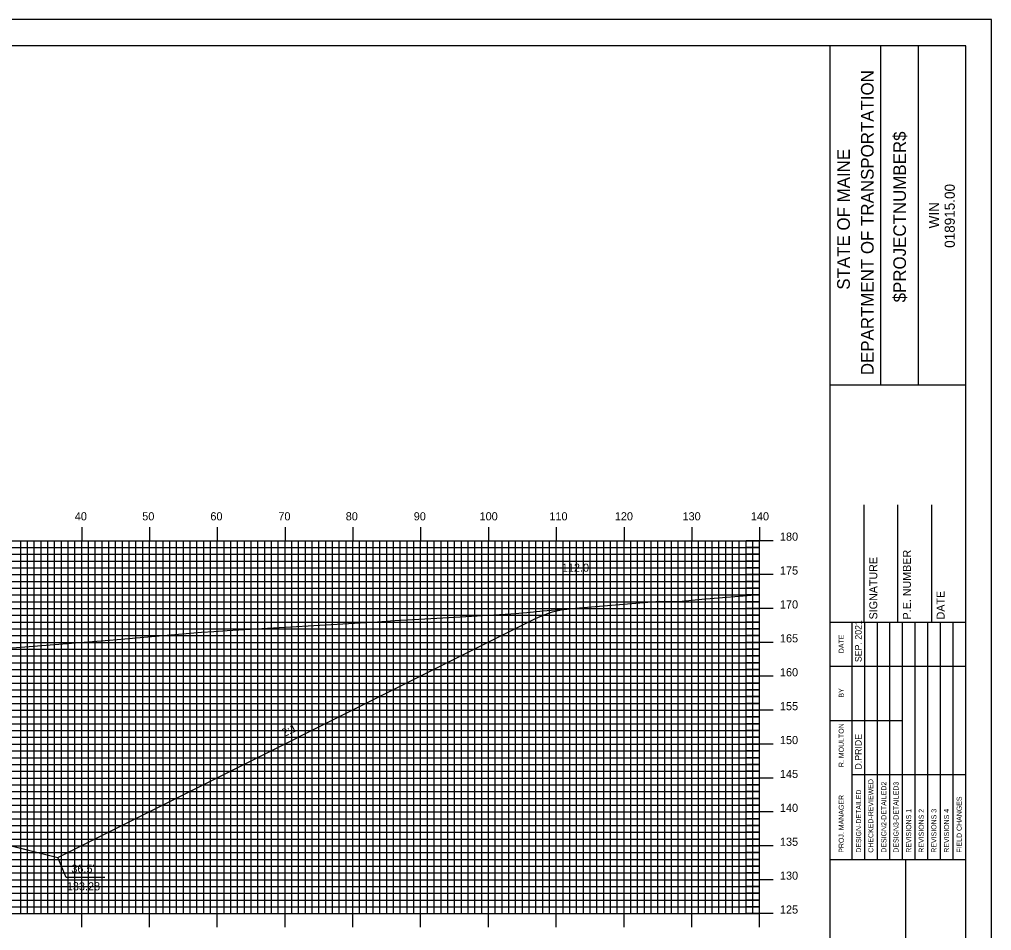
# Model space of a CAD drawing. Extents: x 1783434 to 1783777, y 442591 to 442811.
# Drawn here: x 1783630.8 to 1783774.2, y 442676.2 to 442810.5 of the extents above; entities that cross this region are included whole.
import ezdxf

# ---------------------------------------------------------------- set-up
doc = ezdxf.new("R2010")
doc.units = 0
for name, color, linetype in [('ANNOTATION', 7, 'Continuous'), ('BORDER', 7, 'Continuous'), ('D_Roadway_Centerline', 7, 'Continuous'), ('D_Roadway_SlopeLines', 7, 'Continuous'), ('D_Text_Standard', 7, 'Continuous'), ('H_V ANNOTATION', 7, 'Continuous'), ('MAJOR', 7, 'Continuous'), ('MINOR', 7, 'Continuous'), ('PLOT BOUNDARY', 7, 'Continuous'), ('S_Roadway_Centerline', 7, 'Continuous')]:
    doc.layers.add(name, color=color, linetype=linetype)

msp = doc.modelspace()

# ---------------------------------------------------------------- linework, layer by layer
at = {"layer": 'ANNOTATION'}
msp.add_lwpolyline([(1783643.38, 442683.98), (1783637.68, 442683.98), (1783636.44, 442686.95)], dxfattribs=at)
at = {"layer": 'BORDER'}
for p, q in [((1783750.37, 442596.67), (1783750.37, 442806.67)), ((1783757.83, 442756.66), (1783757.83, 442806.66)), ((1783763.42, 442756.66), (1783763.42, 442806.66)), ((1783750.38, 442756.65), (1783770.37, 442756.65)), ((1783750.38, 442756.65), (1783770.37, 442756.65)), ((1783755.37, 442721.67), (1783755.37, 442738.97)), ((1783755.37, 442721.67), (1783755.37, 442738.97)), ((1783760.37, 442721.67), (1783760.37, 442738.97)), ((1783760.37, 442721.67), (1783760.37, 442738.97)), ((1783765.37, 442721.67), (1783765.37, 442738.97)), ((1783765.37, 442721.67), (1783765.37, 442738.97)), ((1783750.37, 442721.67), (1783770.37, 442721.67)), ((1783750.37, 442721.67), (1783770.37, 442721.67)), ((1783750.37, 442686.67), (1783770.37, 442686.67)), ((1783750.37, 442686.67), (1783770.37, 442686.67)), ((1783761.56, 442616.67), (1783761.56, 442686.67)), ((1783761.56, 442616.67), (1783761.56, 442686.67))]:
    msp.add_line(p, q, dxfattribs=at)
msp.add_lwpolyline([(1783450.37, 442596.67), (1783770.37, 442596.67), (1783770.37, 442806.67), (1783450.37, 442806.67)], close=True, dxfattribs=at)
for points in [[(1783753.6, 442715.17), (1783753.6, 442721.67)], [(1783753.6, 442715.17), (1783753.6, 442721.67)], [(1783755.47, 442686.68), (1783755.47, 442721.67)], [(1783755.47, 442686.68), (1783755.47, 442721.67)], [(1783757.33, 442721.67), (1783757.33, 442686.68)], [(1783757.33, 442721.67), (1783757.33, 442686.68)], [(1783759.19, 442686.68), (1783759.19, 442721.67)], [(1783759.19, 442686.68), (1783759.19, 442721.67)], [(1783761.06, 442686.68), (1783761.06, 442721.67)], [(1783761.06, 442686.68), (1783761.06, 442721.67)], [(1783762.92, 442686.68), (1783762.92, 442721.67)], [(1783762.92, 442686.68), (1783762.92, 442721.67)], [(1783764.78, 442686.68), (1783764.78, 442721.67)], [(1783764.78, 442686.68), (1783764.78, 442721.67)], [(1783766.65, 442686.68), (1783766.65, 442721.67)], [(1783766.65, 442686.68), (1783766.65, 442721.67)], [(1783768.51, 442686.68), (1783768.51, 442721.67)], [(1783768.51, 442686.68), (1783768.51, 442721.67)], [(1783753.6, 442686.68), (1783753.6, 442720.26)], [(1783753.6, 442686.68), (1783753.6, 442720.26)], [(1783750.37, 442715.17), (1783770.37, 442715.17)], [(1783750.37, 442715.17), (1783770.37, 442715.17)], [(1783750.37, 442707.17), (1783753.6, 442707.17)], [(1783750.37, 442707.17), (1783753.6, 442707.17)], [(1783753.6, 442707.17), (1783761.06, 442707.17)], [(1783753.6, 442707.17), (1783761.06, 442707.17)], [(1783753.6, 442699.17), (1783770.37, 442699.17)], [(1783753.6, 442699.17), (1783770.37, 442699.17)]]:
    msp.add_lwpolyline(points, dxfattribs=at)
at = {"layer": 'D_Roadway_Centerline'}
msp.add_lwpolyline([(1783518.66, 442709.45), (1783519.91, 442709.41), (1783521.16, 442709.21), (1783522.41, 442708.84), (1783523.66, 442708.3), (1783565.8, 442687.23), (1783569.8, 442688.23), (1783579.97, 442690.78), (1783587.97, 442691.1), (1783599.97, 442691.34), (1783611.97, 442691.38), (1783619.97, 442691.06), (1783630.15, 442688.52), (1783636.44, 442686.95), (1783706.93, 442722.19), (1783708.18, 442722.75), (1783709.43, 442723.18), (1783710.68, 442723.48), (1783711.93, 442723.64)], dxfattribs=at)
at = {"layer": 'D_Roadway_SlopeLines'}
for points in [[(1783636.44, 442686.95), (1783706.93, 442722.19), (1783708.18, 442722.75), (1783709.43, 442723.18), (1783710.68, 442723.48), (1783711.93, 442723.64)], [(1783619.97, 442691.06), (1783636.44, 442686.95)]]:
    msp.add_lwpolyline(points, dxfattribs=at)
at = {"layer": 'MAJOR'}
for p, q in [((1783639.97, 442735.67), (1783639.97, 442733.67)), ((1783649.97, 442735.67), (1783649.97, 442733.67)), ((1783659.97, 442735.67), (1783659.97, 442733.67)), ((1783669.97, 442735.67), (1783669.97, 442733.67)), ((1783679.97, 442735.67), (1783679.97, 442733.67)), ((1783689.97, 442735.67), (1783689.97, 442733.67)), ((1783699.97, 442735.67), (1783699.97, 442733.67)), ((1783709.97, 442735.67), (1783709.97, 442733.67)), ((1783719.97, 442735.67), (1783719.97, 442733.67)), ((1783729.97, 442735.67), (1783729.97, 442733.67)), ((1783739.97, 442735.67), (1783739.97, 442733.67)), ((1783459.97, 442733.67), (1783739.97, 442733.67)), ((1783459.97, 442733.67), (1783739.97, 442733.67)), ((1783639.97, 442678.67), (1783639.97, 442733.67)), ((1783649.97, 442678.67), (1783649.97, 442733.67)), ((1783659.97, 442678.67), (1783659.97, 442733.67)), ((1783669.97, 442678.67), (1783669.97, 442733.67)), ((1783679.97, 442678.67), (1783679.97, 442733.67)), ((1783689.97, 442678.67), (1783689.97, 442733.67)), ((1783699.97, 442678.67), (1783699.97, 442733.67)), ((1783709.97, 442678.67), (1783709.97, 442733.67)), ((1783719.97, 442678.67), (1783719.97, 442733.67)), ((1783729.97, 442678.67), (1783729.97, 442733.67)), ((1783741.98, 442733.67), (1783737.97, 442733.67)), ((1783739.97, 442678.67), (1783739.97, 442733.67)), ((1783739.97, 442678.67), (1783739.97, 442733.67)), ((1783459.97, 442728.67), (1783739.97, 442728.67)), ((1783741.98, 442728.67), (1783737.97, 442728.67)), ((1783459.97, 442723.67), (1783739.97, 442723.67)), ((1783741.98, 442723.67), (1783737.97, 442723.67)), ((1783459.97, 442718.67), (1783739.97, 442718.67)), ((1783741.98, 442718.67), (1783737.97, 442718.67)), ((1783459.97, 442713.67), (1783739.97, 442713.67)), ((1783741.98, 442713.67), (1783737.97, 442713.67)), ((1783459.97, 442708.67), (1783739.97, 442708.67)), ((1783741.98, 442708.67), (1783737.97, 442708.67)), ((1783459.97, 442703.67), (1783739.97, 442703.67)), ((1783741.98, 442703.67), (1783737.97, 442703.67)), ((1783459.97, 442698.67), (1783739.97, 442698.67)), ((1783741.98, 442698.67), (1783737.97, 442698.67)), ((1783459.97, 442693.67), (1783739.97, 442693.67)), ((1783741.98, 442693.67), (1783737.97, 442693.67)), ((1783459.97, 442688.67), (1783739.97, 442688.67)), ((1783741.98, 442688.67), (1783737.97, 442688.67)), ((1783459.97, 442683.67), (1783739.97, 442683.67)), ((1783741.98, 442683.67), (1783737.97, 442683.67)), ((1783459.97, 442678.67), (1783739.97, 442678.67)), ((1783459.97, 442678.67), (1783739.97, 442678.67)), ((1783639.97, 442676.66), (1783639.97, 442678.67)), ((1783649.97, 442676.66), (1783649.97, 442678.67)), ((1783659.97, 442676.66), (1783659.97, 442678.67)), ((1783669.97, 442676.66), (1783669.97, 442678.67)), ((1783679.97, 442676.66), (1783679.97, 442678.67)), ((1783689.97, 442676.66), (1783689.97, 442678.67)), ((1783699.97, 442676.66), (1783699.97, 442678.67)), ((1783709.97, 442676.66), (1783709.97, 442678.67)), ((1783719.97, 442676.66), (1783719.97, 442678.67)), ((1783729.97, 442676.66), (1783729.97, 442678.67)), ((1783741.98, 442678.67), (1783737.97, 442678.67)), ((1783739.97, 442676.66), (1783739.97, 442678.67))]:
    msp.add_line(p, q, dxfattribs=at)
at = {"layer": 'MINOR'}
for p, q in [((1783459.97, 442732.67), (1783739.97, 442732.67)), ((1783630.97, 442678.67), (1783630.97, 442733.67)), ((1783631.97, 442678.67), (1783631.97, 442733.67)), ((1783632.97, 442678.67), (1783632.97, 442733.67)), ((1783633.97, 442678.67), (1783633.97, 442733.67)), ((1783634.97, 442678.67), (1783634.97, 442733.67)), ((1783635.97, 442678.67), (1783635.97, 442733.67)), ((1783636.97, 442678.67), (1783636.97, 442733.67)), ((1783637.97, 442678.67), (1783637.97, 442733.67)), ((1783638.97, 442678.67), (1783638.97, 442733.67)), ((1783640.97, 442678.67), (1783640.97, 442733.67)), ((1783641.97, 442678.67), (1783641.97, 442733.67)), ((1783642.97, 442678.67), (1783642.97, 442733.67)), ((1783643.97, 442678.67), (1783643.97, 442733.67)), ((1783644.97, 442678.67), (1783644.97, 442733.67)), ((1783645.97, 442678.67), (1783645.97, 442733.67)), ((1783646.97, 442678.67), (1783646.97, 442733.67)), ((1783647.97, 442678.67), (1783647.97, 442733.67)), ((1783648.97, 442678.67), (1783648.97, 442733.67)), ((1783650.97, 442678.67), (1783650.97, 442733.67)), ((1783651.97, 442678.67), (1783651.97, 442733.67)), ((1783652.97, 442678.67), (1783652.97, 442733.67)), ((1783653.97, 442678.67), (1783653.97, 442733.67)), ((1783654.97, 442678.67), (1783654.97, 442733.67)), ((1783655.97, 442678.67), (1783655.97, 442733.67)), ((1783656.97, 442678.67), (1783656.97, 442733.67)), ((1783657.97, 442678.67), (1783657.97, 442733.67)), ((1783658.97, 442678.67), (1783658.97, 442733.67)), ((1783660.97, 442678.67), (1783660.97, 442733.67)), ((1783661.97, 442678.67), (1783661.97, 442733.67)), ((1783662.97, 442678.67), (1783662.97, 442733.67)), ((1783663.97, 442678.67), (1783663.97, 442733.67)), ((1783664.97, 442678.67), (1783664.97, 442733.67)), ((1783665.97, 442678.67), (1783665.97, 442733.67)), ((1783666.97, 442678.67), (1783666.97, 442733.67)), ((1783667.97, 442678.67), (1783667.97, 442733.67)), ((1783668.97, 442678.67), (1783668.97, 442733.67)), ((1783670.97, 442678.67), (1783670.97, 442733.67)), ((1783671.97, 442678.67), (1783671.97, 442733.67)), ((1783672.97, 442678.67), (1783672.97, 442733.67)), ((1783673.97, 442678.67), (1783673.97, 442733.67)), ((1783674.97, 442678.67), (1783674.97, 442733.67)), ((1783675.97, 442678.67), (1783675.97, 442733.67)), ((1783676.97, 442678.67), (1783676.97, 442733.67)), ((1783677.97, 442678.67), (1783677.97, 442733.67)), ((1783678.97, 442678.67), (1783678.97, 442733.67)), ((1783680.97, 442678.67), (1783680.97, 442733.67)), ((1783681.97, 442678.67), (1783681.97, 442733.67)), ((1783682.97, 442678.67), (1783682.97, 442733.67)), ((1783683.97, 442678.67), (1783683.97, 442733.67)), ((1783684.97, 442678.67), (1783684.97, 442733.67)), ((1783685.97, 442678.67), (1783685.97, 442733.67)), ((1783686.97, 442678.67), (1783686.97, 442733.67)), ((1783687.97, 442678.67), (1783687.97, 442733.67)), ((1783688.97, 442678.67), (1783688.97, 442733.67)), ((1783690.97, 442678.67), (1783690.97, 442733.67)), ((1783691.97, 442678.67), (1783691.97, 442733.67)), ((1783692.97, 442678.67), (1783692.97, 442733.67)), ((1783693.97, 442678.67), (1783693.97, 442733.67)), ((1783694.97, 442678.67), (1783694.97, 442733.67)), ((1783695.97, 442678.67), (1783695.97, 442733.67)), ((1783696.97, 442678.67), (1783696.97, 442733.67)), ((1783697.97, 442678.67), (1783697.97, 442733.67)), ((1783698.97, 442678.67), (1783698.97, 442733.67)), ((1783700.97, 442678.67), (1783700.97, 442733.67)), ((1783701.97, 442678.67), (1783701.97, 442733.67)), ((1783702.97, 442678.67), (1783702.97, 442733.67)), ((1783703.97, 442678.67), (1783703.97, 442733.67)), ((1783704.97, 442678.67), (1783704.97, 442733.67)), ((1783705.97, 442678.67), (1783705.97, 442733.67)), ((1783706.97, 442678.67), (1783706.97, 442733.67)), ((1783707.97, 442678.67), (1783707.97, 442733.67)), ((1783708.97, 442678.67), (1783708.97, 442733.67)), ((1783710.97, 442678.67), (1783710.97, 442733.67)), ((1783711.97, 442678.67), (1783711.97, 442733.67)), ((1783712.97, 442678.67), (1783712.97, 442733.67)), ((1783713.97, 442678.67), (1783713.97, 442733.67)), ((1783714.97, 442678.67), (1783714.97, 442733.67)), ((1783715.97, 442678.67), (1783715.97, 442733.67)), ((1783716.97, 442678.67), (1783716.97, 442733.67)), ((1783717.97, 442678.67), (1783717.97, 442733.67)), ((1783718.97, 442678.67), (1783718.97, 442733.67)), ((1783720.97, 442678.67), (1783720.97, 442733.67)), ((1783721.97, 442678.67), (1783721.97, 442733.67)), ((1783722.97, 442678.67), (1783722.97, 442733.67)), ((1783723.97, 442678.67), (1783723.97, 442733.67)), ((1783724.97, 442678.67), (1783724.97, 442733.67)), ((1783725.97, 442678.67), (1783725.97, 442733.67)), ((1783726.97, 442678.67), (1783726.97, 442733.67)), ((1783727.97, 442678.67), (1783727.97, 442733.67)), ((1783728.97, 442678.67), (1783728.97, 442733.67)), ((1783730.97, 442678.67), (1783730.97, 442733.67)), ((1783731.97, 442678.67), (1783731.97, 442733.67)), ((1783732.97, 442678.67), (1783732.97, 442733.67)), ((1783733.97, 442678.67), (1783733.97, 442733.67)), ((1783734.97, 442678.67), (1783734.97, 442733.67)), ((1783735.97, 442678.67), (1783735.97, 442733.67)), ((1783736.97, 442678.67), (1783736.97, 442733.67)), ((1783737.97, 442678.67), (1783737.97, 442733.67)), ((1783739.97, 442732.67), (1783737.97, 442732.67)), ((1783738.97, 442678.67), (1783738.97, 442733.67)), ((1783459.97, 442731.67), (1783739.97, 442731.67)), ((1783739.97, 442731.67), (1783737.97, 442731.67)), ((1783459.97, 442730.67), (1783739.97, 442730.67)), ((1783739.97, 442730.67), (1783737.97, 442730.67)), ((1783459.97, 442729.67), (1783739.97, 442729.67)), ((1783739.97, 442729.67), (1783737.97, 442729.67)), ((1783459.97, 442727.67), (1783739.97, 442727.67)), ((1783739.97, 442727.67), (1783737.97, 442727.67)), ((1783459.97, 442726.67), (1783739.97, 442726.67)), ((1783459.97, 442725.67), (1783739.97, 442725.67)), ((1783739.97, 442726.67), (1783737.97, 442726.67)), ((1783739.97, 442725.67), (1783737.97, 442725.67)), ((1783459.97, 442724.67), (1783739.97, 442724.67)), ((1783739.97, 442724.67), (1783737.97, 442724.67)), ((1783459.97, 442722.67), (1783739.97, 442722.67)), ((1783739.97, 442722.67), (1783737.97, 442722.67)), ((1783459.97, 442721.67), (1783739.97, 442721.67)), ((1783739.97, 442721.67), (1783737.97, 442721.67)), ((1783459.97, 442720.67), (1783739.97, 442720.67)), ((1783459.97, 442719.67), (1783739.97, 442719.67)), ((1783739.97, 442720.67), (1783737.97, 442720.67)), ((1783739.97, 442719.67), (1783737.97, 442719.67)), ((1783459.97, 442717.67), (1783739.97, 442717.67)), ((1783739.97, 442717.67), (1783737.97, 442717.67)), ((1783459.97, 442716.67), (1783739.97, 442716.67)), ((1783459.97, 442715.67), (1783739.97, 442715.67)), ((1783739.97, 442716.67), (1783737.97, 442716.67)), ((1783739.97, 442715.67), (1783737.97, 442715.67)), ((1783459.97, 442714.67), (1783739.97, 442714.67)), ((1783739.97, 442714.67), (1783737.97, 442714.67)), ((1783459.97, 442712.67), (1783739.97, 442712.67)), ((1783739.97, 442712.67), (1783737.97, 442712.67)), ((1783459.97, 442711.67), (1783739.97, 442711.67)), ((1783739.97, 442711.67), (1783737.97, 442711.67)), ((1783459.97, 442710.67), (1783739.97, 442710.67)), ((1783459.97, 442709.67), (1783739.97, 442709.67)), ((1783739.97, 442710.67), (1783737.97, 442710.67)), ((1783739.97, 442709.67), (1783737.97, 442709.67)), ((1783459.97, 442707.67), (1783739.97, 442707.67)), ((1783739.97, 442707.67), (1783737.97, 442707.67)), ((1783459.97, 442706.67), (1783739.97, 442706.67)), ((1783459.97, 442705.67), (1783739.97, 442705.67)), ((1783739.97, 442706.67), (1783737.97, 442706.67)), ((1783739.97, 442705.67), (1783737.97, 442705.67)), ((1783459.97, 442704.67), (1783739.97, 442704.67)), ((1783739.97, 442704.67), (1783737.97, 442704.67)), ((1783459.97, 442702.67), (1783739.97, 442702.67)), ((1783739.97, 442702.67), (1783737.97, 442702.67)), ((1783459.97, 442701.67), (1783739.97, 442701.67)), ((1783739.97, 442701.67), (1783737.97, 442701.67)), ((1783459.97, 442700.67), (1783739.97, 442700.67)), ((1783459.97, 442699.67), (1783739.97, 442699.67)), ((1783739.97, 442700.67), (1783737.97, 442700.67)), ((1783739.97, 442699.67), (1783737.97, 442699.67)), ((1783459.97, 442697.67), (1783739.97, 442697.67)), ((1783739.97, 442697.67), (1783737.97, 442697.67)), ((1783459.97, 442696.67), (1783739.97, 442696.67)), ((1783459.97, 442695.67), (1783739.97, 442695.67)), ((1783739.97, 442696.67), (1783737.97, 442696.67)), ((1783739.97, 442695.67), (1783737.97, 442695.67)), ((1783459.97, 442694.67), (1783739.97, 442694.67)), ((1783739.97, 442694.67), (1783737.97, 442694.67)), ((1783459.97, 442692.67), (1783739.97, 442692.67)), ((1783739.97, 442692.67), (1783737.97, 442692.67)), ((1783459.97, 442691.67), (1783739.97, 442691.67)), ((1783739.97, 442691.67), (1783737.97, 442691.67)), ((1783459.97, 442690.67), (1783739.97, 442690.67)), ((1783459.97, 442689.67), (1783739.97, 442689.67)), ((1783739.97, 442690.67), (1783737.97, 442690.67)), ((1783739.97, 442689.67), (1783737.97, 442689.67)), ((1783459.97, 442687.67), (1783739.97, 442687.67)), ((1783739.97, 442687.67), (1783737.97, 442687.67)), ((1783459.97, 442686.67), (1783739.97, 442686.67)), ((1783459.97, 442685.67), (1783739.97, 442685.67)), ((1783739.97, 442686.67), (1783737.97, 442686.67)), ((1783739.97, 442685.67), (1783737.97, 442685.67)), ((1783459.97, 442684.67), (1783739.97, 442684.67)), ((1783739.97, 442684.67), (1783737.97, 442684.67)), ((1783459.97, 442682.67), (1783739.97, 442682.67)), ((1783739.97, 442682.67), (1783737.97, 442682.67)), ((1783459.97, 442681.67), (1783739.97, 442681.67)), ((1783739.97, 442681.67), (1783737.97, 442681.67)), ((1783459.97, 442680.67), (1783739.97, 442680.67)), ((1783459.97, 442679.67), (1783739.97, 442679.67)), ((1783739.97, 442680.67), (1783737.97, 442680.67)), ((1783739.97, 442679.67), (1783737.97, 442679.67))]:
    msp.add_line(p, q, dxfattribs=at)
at = {"layer": 'PLOT BOUNDARY'}
msp.add_lwpolyline([(1783434.19, 442590.55), (1783774.19, 442590.55), (1783774.19, 442810.55), (1783434.19, 442810.55)], close=True, dxfattribs=at)
at = {"layer": 'S_Roadway_Centerline'}
msp.add_lwpolyline([(1783629.72, 442717.89), (1783644.08, 442718.99), (1783657.62, 442720.17), (1783659.46, 442720.3), (1783661.43, 442720.43), (1783683.59, 442721.68), (1783686.17, 442721.9), (1783694.11, 442722.32), (1783703.25, 442722.86), (1783705.63, 442723.06), (1783708.05, 442723.33), (1783725.26, 442724.73), (1783728.07, 442724.72), (1783731.43, 442725.07), (1783739.97, 442725.72)], dxfattribs=at)

# ---------------------------------------------------------------- texts
at = {"layer": 'ANNOTATION'}
msp.add_text('2:1', height=1.2, rotation=26.5651, dxfattribs=at).set_placement((1783669.83, 442704.68))
for s, p in [("36.5'", (1783638.44, 442684.7)), ('133.28', (1783637.77, 442682.1))]:
    msp.add_text(s, height=1.2, dxfattribs=at).set_placement(p)
at = {"layer": 'BORDER'}
for s, height, p in [('DEPARTMENT OF TRANSPORTATION', 1.8635, (1783756.79, 442758.08)), ('$PROJECTNUMBER$', 1.8635, (1783761.56, 442768.82)), ('STATE OF MAINE', 1.8635, (1783753.28, 442770.69)), ('018915.00', 1.491, (1783768.76, 442776.86)), ('WIN', 1.491, (1783766.45, 442779.73)), ('SIGNATURE', 1.181, (1783757.33, 442722.06)), ('SIGNATURE', 1.181, (1783757.33, 442722.06)), ('P.E. NUMBER', 1.1811, (1783762.29, 442722.06)), ('P.E. NUMBER', 1.1811, (1783762.29, 442722.06)), ('DATE', 1.181, (1783767.26, 442722.06)), ('DATE', 1.181, (1783767.26, 442722.06)), ('SEP. 2021', 0.969, (1783755.02, 442715.76)), ('DATE', 0.743, (1783752.38, 442717.08)), ('DATE', 0.743, (1783752.38, 442717.08)), ('BY', 0.743, (1783752.38, 442710.54)), ('BY', 0.743, (1783752.38, 442710.54)), ('R. MOULTON', 0.745, (1783752.38, 442700.28)), ('D.PRIDE', 0.969, (1783755.02, 442699.92)), ('CHECKED-REVIEWED', 0.7455, (1783756.74, 442687.65)), ('CHECKED-REVIEWED', 0.7455, (1783756.74, 442687.65)), ('DESIGN2-DETAILED2', 0.7455, (1783758.67, 442687.65)), ('DESIGN2-DETAILED2', 0.7455, (1783758.67, 442687.65)), ('DESIGN3-DETAILED3', 0.7455, (1783760.46, 442687.65)), ('DESIGN3-DETAILED3', 0.7455, (1783760.46, 442687.65)), ('PROJ. MANAGER', 0.7455, (1783752.38, 442687.65)), ('PROJ. MANAGER', 0.7455, (1783752.38, 442687.65)), ('DESIGN-DETAILED', 0.7455, (1783754.95, 442687.65)), ('DESIGN-DETAILED', 0.7455, (1783754.95, 442687.65)), ('FIELD CHANGES', 0.7455, (1783769.78, 442687.65)), ('FIELD CHANGES', 0.7455, (1783769.78, 442687.65)), ('REVISIONS 1', 0.7455, (1783762.33, 442687.65)), ('REVISIONS 1', 0.7455, (1783762.33, 442687.65)), ('REVISIONS 2', 0.7455, (1783764.19, 442687.65)), ('REVISIONS 2', 0.7455, (1783764.19, 442687.65)), ('REVISIONS 3', 0.7455, (1783766.05, 442687.65)), ('REVISIONS 3', 0.7455, (1783766.05, 442687.65)), ('REVISIONS 4', 0.7455, (1783767.92, 442687.65)), ('REVISIONS 4', 0.7455, (1783767.92, 442687.65))]:
    msp.add_text(s, height=height, rotation=90, dxfattribs=at).set_placement(p)
at = {"layer": 'D_Text_Standard'}
msp.add_text("112.0'", height=1.2, dxfattribs=at).set_placement((1783710.79, 442729.09))
at = {"layer": 'H_V ANNOTATION'}
for s, p in [('40', (1783638.95, 442736.67)), ('50', (1783648.9, 442736.67)), ('60', (1783658.95, 442736.67)), ('70', (1783668.98, 442736.67)), ('80', (1783678.92, 442736.67)), ('90', (1783688.95, 442736.67)), ('100', (1783698.66, 442736.67)), ('110', (1783708.96, 442736.67)), ('120', (1783718.61, 442736.67)), ('130', (1783728.6, 442736.67)), ('140', (1783738.68, 442736.67)), ('180', (1783742.97, 442733.67)), ('175', (1783742.97, 442728.67)), ('170', (1783742.97, 442723.67)), ('165', (1783742.97, 442718.67)), ('160', (1783742.97, 442713.67)), ('155', (1783742.97, 442708.67)), ('150', (1783742.97, 442703.67)), ('145', (1783742.97, 442698.67)), ('140', (1783742.97, 442693.67)), ('135', (1783742.97, 442688.67)), ('130', (1783742.97, 442683.67)), ('125', (1783742.97, 442678.67))]:
    msp.add_text(s, height=1.2, dxfattribs=at).set_placement(p)

doc.saveas('drawing.dxf')
